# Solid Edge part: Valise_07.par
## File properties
Author: Bernard DUMAS
Template: Normal.par
Last saved by: FR026244
Revision: 11
Application: Solid Edge
Material: Bois, Frêne
Style de face: Jaune kaki
Style de remplissage: Liège
Style virtuel: Frêne verni
Coef. of Thermal Exp: 0.0
Thermal Conductivity: 0.0
Specific Heat: 0.0
Modulus of Elasticity: 0.0
Poission's Ratio: 0.0
Yield Stress: 0.0
Ultimate Stress: 0.0
Elongation: 0.0
Densité: 460.000 kg/m^3
Précision: 0.9900
Document Number: 07
Revision: a
Project Name: Slamson
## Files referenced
..\Valise_Salmson.asm
bD:\Documents and Settings\FR026244\Mes Documents\Bernard\Slamson\Valise-Salmson\Valise_Salmson.asm
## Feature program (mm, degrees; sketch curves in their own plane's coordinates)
sketch for "unnamed Protrusion 1" plane through (0, 0, 0) normal (0, -1, 0) x-axis (1, 0, 0)
extrude "unnamed Protrusion 1" add finite 6 along -normal
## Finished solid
Body 1: solid body, 6 faces, 12 edges, 8 vertices.
  Faces by surface: plane 6
  Edges by curve: line 12
Bounding box of the edges (mm): 498.646 x 6.000 x 103.000, from (-47, 0, 3) to (451.6459, 6, 106).
Planar faces by outward normal: +y 1, +z 1, -x 1, -y 1, -z 1, oblique 1
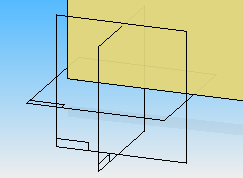
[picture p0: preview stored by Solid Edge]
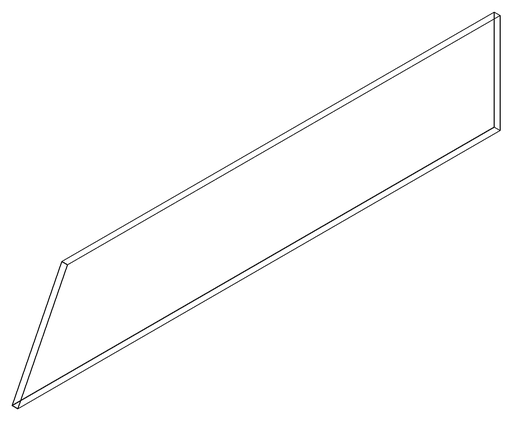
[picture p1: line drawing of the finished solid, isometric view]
